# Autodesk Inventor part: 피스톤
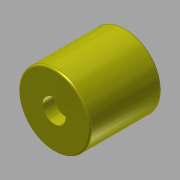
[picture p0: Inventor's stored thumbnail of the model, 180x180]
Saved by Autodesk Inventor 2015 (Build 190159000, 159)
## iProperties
Created: 2018-01
Part Number: 피스톤
Material: 강철, 탄소
Document SubType Name: Modeling
Designer: mduedu
Density: 7.87 g/cm^3
Appearance: 노란색
Mass: 44.9853 g
Surface Area: 21.9333 cm^2
Volume: 5.71605 cm^3
Author: mduedu
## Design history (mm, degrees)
sketch "스케치1"
  geometry: C1 r 10 at (0, 0); 1 further point
  constraints: 1 centre point, 1 coincident
  dimensions: "d0" = 20 diameter of C1
extrude "돌출1" new body sketch "스케치1" distance "d1" = 20; taper "d2" = 0 deg
hole "구멍1" diameter "d5" = 7; stored, may be unused: countersink angle "d9" = 90 deg, drill point angle "d11" = 0 deg; dims "d6" = 6, "d7" = 4, "d8" = 2, "d10" = 10, "d12" = 10, "d13" = 10
chamfer "모따기1" distance "d14" = 0.5; stored, may be unused: second distance "d15" = 2, angle "d16" = 45 deg
fillet "모깎기1" dims "d17" = 0.5
sketch "스케치2"
  geometry: 2 further points
  constraints: 1 coincident
sketch "스케치3"
  geometry: 2 further points
  constraints: 1 coincident
hole "구멍2" sketch "스케치3" at (0, 0) diameter "d18" = 3.4; stored, may be unused: countersink angle "d22" = 90 deg, drill point angle "d24" = 0 deg; dims "d19" = 6, "d20" = 6.5, "d21" = 3.4, "d23" = 8
node "솔리드1"
